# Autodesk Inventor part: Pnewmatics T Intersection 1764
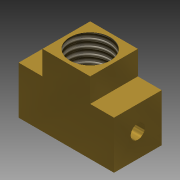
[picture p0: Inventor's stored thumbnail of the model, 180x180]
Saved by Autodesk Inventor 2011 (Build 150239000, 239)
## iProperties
Created: 2010-02
Part Number: Pnewmatics T Intersection 1764
Document SubType Name: Modeling
Designer: jgehrig
Density: 1 g/cm^3
Author: jgehrig
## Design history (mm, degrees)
sketch "Sketch1"
  geometry: L1 (-25.271, 28.178)-(-25.271, 21.828); L2 (-25.271, 21.828)-(-31.621, 21.828); L3 (-31.621, 21.828)-(-31.621, 9.128); L4 (-31.621, 9.128)-(-6.221, 9.128); L5 (-6.221, 9.128)-(-6.221, 21.828); L6 (-6.221, 21.828)-(-12.571, 21.828); L7 (-12.571, 21.828)-(-12.571, 28.178); L8 (-12.571, 28.178)-(-25.271, 28.178); 1 further point
  constraints: 16 end point, 4 parallel, 3 perpendicular, 1 vertical
  dimensions: "d0" = 25.4 distance of L3.end L4.end; "d1" = 6.35 distance of L1.end L2.end; "d2" = 12.7 distance of L7.end L1.start; "d3" = 6.35 distance of L6.end L7.end; "d4" = 12.7 distance of L4.end L5.end; "d5" = 12.7 distance of L2.end L3.end
extrude "Extrusion1" new body sketch "Sketch1" distance "d6" = 12.7; taper "d7" = 0 deg
sketch "Sketch2"
  geometry: C1 r 5.397 at (6.35, -6.35); 1 further point
  constraints: 1 centre point
  dimensions: "d8" = 10.795 diameter of C1
extrude "Extrusion2" cut sketch "Sketch2" distance "d9" = 16.51; taper "d10" = 0 deg
thread "Thread1" dims "d11" = 25.4, "d12" = 0
sketch "Sketch3"
  geometry: C1 r 1.905 at (-6.35, 6.35); 1 further point
  constraints: 1 centre point
  dimensions: "d13" = 3.81 diameter of C1
extrude "Extrusion3" cut sketch "Sketch3" stored distance "d14" = 16.51; taper "d15" = 0 deg
body "Solid1"
